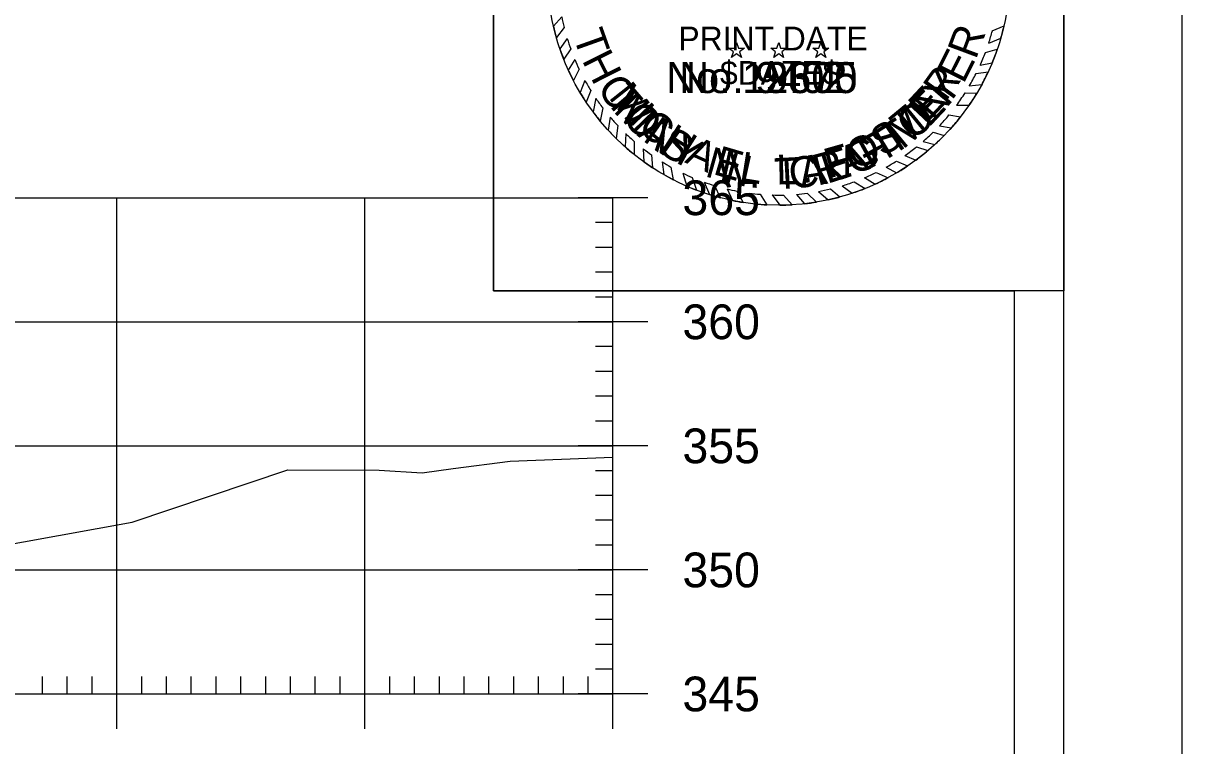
# Model space of a CAD drawing. Extents: x 1368910 to 1369601, y 380116 to 380950.
# Drawn here: x 1369553.81 to 1369600.52, y 380680.67 to 380709.8 of the extents above; entities that cross this region are included whole.
import ezdxf

# ---------------------------------------------------------------- set-up
doc = ezdxf.new("R2010")
doc.units = 0
for name, color, linetype in [('R_Axis', 7, 'Continuous'), ('R_Axis Annot', 7, 'Continuous'), ('R_Border', 7, 'Continuous'), ('R_Exist Surface', 7, 'Continuous'), ('R_Grid', 7, 'Continuous'), ('R_No Plot', 7, 'Continuous'), ('STAMP_PE_CRAFTON', 7, 'Continuous'), ('STAMP_PE_FOSTER', 7, 'Continuous'), ('STAMP_PE_SEAL-INFO', 7, 'Continuous'), ('STAMP_PE_TAEGTMEYER', 7, 'Continuous'), ('STAMP_PE_TXT', 7, 'Continuous'), ('STAMP_PRELIMINARY', 7, 'Continuous')]:
    doc.layers.add(name, color=color, linetype=linetype)

msp = doc.modelspace()

# ---------------------------------------------------------------- linework, layer by layer
at = {"layer": 'R_Axis'}
for p, q in [((1369578.99, 380702.759), (1369576.19, 380702.759)), ((1369577.59, 380682.759), (1369577.59, 380702.759)), ((1369577.59, 380701.759), (1369576.89, 380701.759)), ((1369577.59, 380700.759), (1369576.89, 380700.759)), ((1369577.59, 380699.759), (1369576.89, 380699.759)), ((1369577.59, 380698.759), (1369576.89, 380698.759)), ((1369578.99, 380697.759), (1369576.19, 380697.759)), ((1369577.59, 380696.759), (1369576.89, 380696.759)), ((1369577.59, 380695.759), (1369576.89, 380695.759)), ((1369577.59, 380694.759), (1369576.89, 380694.759)), ((1369577.59, 380693.759), (1369576.89, 380693.759)), ((1369578.99, 380692.759), (1369576.19, 380692.759)), ((1369577.59, 380691.759), (1369576.89, 380691.759)), ((1369577.59, 380690.759), (1369576.89, 380690.759)), ((1369577.59, 380689.759), (1369576.89, 380689.759)), ((1369577.59, 380688.759), (1369576.89, 380688.759)), ((1369578.99, 380687.759), (1369576.19, 380687.759)), ((1369577.59, 380686.759), (1369576.89, 380686.759)), ((1369577.59, 380685.759), (1369576.89, 380685.759)), ((1369577.59, 380684.759), (1369576.89, 380684.759)), ((1369557.59, 380681.359), (1369557.59, 380684.159)), ((1369567.59, 380681.359), (1369567.59, 380684.159)), ((1369577.59, 380681.359), (1369577.59, 380684.159)), ((1369577.59, 380683.759), (1369576.89, 380683.759)), ((1369554.59, 380682.759), (1369554.59, 380683.459)), ((1369555.59, 380682.759), (1369555.59, 380683.459)), ((1369556.59, 380682.759), (1369556.59, 380683.459)), ((1369558.59, 380682.759), (1369558.59, 380683.459)), ((1369559.59, 380682.759), (1369559.59, 380683.459)), ((1369560.59, 380682.759), (1369560.59, 380683.459)), ((1369561.59, 380682.759), (1369561.59, 380683.459)), ((1369562.59, 380682.759), (1369562.59, 380683.459)), ((1369563.59, 380682.759), (1369563.59, 380683.459)), ((1369564.59, 380682.759), (1369564.59, 380683.459)), ((1369565.59, 380682.759), (1369565.59, 380683.459)), ((1369566.59, 380682.759), (1369566.59, 380683.459)), ((1369568.59, 380682.759), (1369568.59, 380683.459)), ((1369569.59, 380682.759), (1369569.59, 380683.459)), ((1369570.59, 380682.759), (1369570.59, 380683.459)), ((1369571.59, 380682.759), (1369571.59, 380683.459)), ((1369572.59, 380682.759), (1369572.59, 380683.459)), ((1369573.59, 380682.759), (1369573.59, 380683.459)), ((1369574.59, 380682.759), (1369574.59, 380683.459)), ((1369575.59, 380682.759), (1369575.59, 380683.459)), ((1369576.59, 380682.759), (1369576.59, 380683.459)), ((1369297.59, 380682.759), (1369577.59, 380682.759)), ((1369578.99, 380682.759), (1369576.19, 380682.759))]:
    msp.add_line(p, q, dxfattribs=at)
at = {"layer": 'R_Border'}
msp.add_line((1369595.77, 380527.759), (1369595.77, 380733.219), dxfattribs=at)
at = {"layer": 'R_Exist Surface'}
msp.add_lwpolyline([(1369517.72, 380691.662), (1369530.654, 380692.291), (1369534.092, 380690.01), (1369537.049, 380687.943), (1369544.245, 380688.244), (1369546.58, 380688.221), (1369549.426, 380688.092), (1369558.204, 380689.69), (1369564.489, 380691.792), (1369568.163, 380691.776), (1369569.894, 380691.676), (1369571.144, 380691.841), (1369573.442, 380692.14), (1369577.59, 380692.301)], dxfattribs=at)
at = {"layer": 'R_Grid'}
for p, q in [((1369297.59, 380702.759), (1369577.59, 380702.759)), ((1369557.59, 380682.759), (1369557.59, 380702.759)), ((1369567.59, 380682.759), (1369567.59, 380702.759)), ((1369577.59, 380682.759), (1369577.59, 380702.759)), ((1369297.59, 380697.759), (1369577.59, 380697.759)), ((1369297.59, 380692.759), (1369577.59, 380692.759)), ((1369297.59, 380687.759), (1369577.59, 380687.759)), ((1369297.59, 380682.759), (1369577.59, 380682.759))]:
    msp.add_line(p, q, dxfattribs=at)
at = {"layer": 'R_No Plot'}
for points in [[(1369267.182, 380737.113), (1369600.522, 380737.113), (1369600.522, 380523.776), (1369267.182, 380523.776)], [(1369593.77, 380632.489), (1369281.59, 380632.489), (1369281.59, 380731.219), (1369531.13, 380731.219), (1369531.13, 380721.339), (1369548.67, 380721.339), (1369572.77, 380721.339), (1369572.77, 380699.006), (1369593.77, 380699.006)], [(1369281.59, 380731.219), (1369531.13, 380731.219), (1369531.13, 380721.339), (1369548.67, 380721.339), (1369572.77, 380721.339), (1369572.77, 380699.006), (1369593.77, 380699.006), (1369593.77, 380529.759), (1369281.59, 380529.759)], [(1369572.77, 380723.339), (1369595.77, 380723.339), (1369595.77, 380699.006), (1369572.77, 380699.006)]]:
    msp.add_lwpolyline(points, close=True, dxfattribs=at)
at = {"layer": 'STAMP_PE_SEAL-INFO'}
for p, q in [((1369575.527, 380710.046), (1369575.188, 380709.678)), ((1369575.621, 380709.627), (1369575.308, 380709.212)), ((1369592.883, 380709.488), (1369593.355, 380709.69)), ((1369575.744, 380709.18), (1369575.45, 380708.762)), ((1369592.736, 380708.994), (1369593.227, 380709.195)), ((1369575.885, 380708.757), (1369575.604, 380708.345)), ((1369592.602, 380708.614), (1369593.084, 380708.745)), ((1369576.052, 380708.331), (1369575.79, 380707.908)), ((1369576.223, 380707.947), (1369575.996, 380707.486)), ((1369592.227, 380707.763), (1369592.715, 380707.832)), ((1369592.388, 380708.1), (1369592.876, 380708.196)), ((1369576.458, 380707.489), (1369576.267, 380706.999)), ((1369591.954, 380707.265), (1369592.455, 380707.319)), ((1369576.694, 380707.085), (1369576.51, 380706.614)), ((1369591.783, 380706.984), (1369592.26, 380706.978)), ((1369576.896, 380706.773), (1369576.787, 380706.221)), ((1369577.177, 380706.383), (1369577.075, 380705.852)), ((1369591.443, 380706.49), (1369591.948, 380706.493)), ((1369577.481, 380706.005), (1369577.394, 380705.485)), ((1369591.135, 380706.096), (1369591.597, 380706.017)), ((1369577.784, 380705.668), (1369577.722, 380705.146)), ((1369590.752, 380705.663), (1369591.229, 380705.578)), ((1369578.106, 380705.343), (1369578.076, 380704.813)), ((1369578.45, 380705.03), (1369578.447, 380704.501)), ((1369590.091, 380705.031), (1369590.563, 380704.903)), ((1369590.497, 380705.404), (1369590.938, 380705.266)), ((1369578.81, 380704.735), (1369578.829, 380704.211)), ((1369579.149, 380704.486), (1369579.185, 380703.968)), ((1369589.821, 380704.807), (1369590.288, 380704.662)), ((1369579.576, 380704.204), (1369579.637, 380703.692)), ((1369589.016, 380704.236), (1369589.466, 380704.041)), ((1369589.36, 380704.464), (1369589.799, 380704.275)), ((1369579.926, 380703.998), (1369580.017, 380703.485)), ((1369580.407, 380703.748), (1369580.564, 380703.227)), ((1369580.78, 380703.58), (1369580.953, 380703.069)), ((1369587.735, 380703.569), (1369588.158, 380703.308)), ((1369588.194, 380703.778), (1369588.678, 380703.566)), ((1369588.602, 380703.991), (1369589.019, 380703.759)), ((1369581.272, 380703.387), (1369581.482, 380702.885)), ((1369581.682, 380703.252), (1369581.908, 380702.763)), ((1369582.19, 380703.114), (1369582.402, 380702.648)), ((1369586.363, 380703.117), (1369586.741, 380702.792)), ((1369586.823, 380703.241), (1369587.239, 380702.944)), ((1369587.315, 380703.404), (1369587.758, 380703.136)), ((1369582.587, 380703.028), (1369582.834, 380702.57)), ((1369583.088, 380702.947), (1369583.328, 380702.506)), ((1369583.524, 380702.899), (1369583.798, 380702.471)), ((1369584.009, 380702.872), (1369584.311, 380702.459)), ((1369584.469, 380702.87), (1369584.812, 380702.474)), ((1369584.987, 380702.897), (1369585.313, 380702.517)), ((1369585.425, 380702.943), (1369585.798, 380702.585)), ((1369585.871, 380703.013), (1369586.259, 380702.673))]:
    msp.add_line(p, q, dxfattribs=at)
for radius, start, end in [(9.323, 193.0369, 195.9973), (8.914, 191.2274, 193.9858), (9.323, 343.8925, 347.035), (8.914, 196.9675, 199.8353), (8.914, 341.777, 345.0925), (9.323, 198.8967, 201.6281), (9.323, 337.3837, 340.9933), (8.914, 202.7761, 205.4791), (8.914, 335.6038, 339.1858), (9.323, 204.5479, 207.4328), (8.914, 329.5549, 333.2076), (9.323, 331.4037, 334.9332), (8.914, 208.7883, 211.7934), (9.323, 210.8636, 213.6571), (8.914, 323.5851, 327.4407), (9.323, 325.4405, 328.9872), (8.914, 214.1838, 217.2747), (9.323, 216.6115, 219.491), (8.914, 220.3909, 223.3056), (8.914, 316.6531, 320.3711), (9.323, 318.2846, 321.8043), (9.323, 222.48, 225.3801), (8.914, 226.2494, 229.2407), (8.914, 310.7744, 314.3161), (9.323, 312.4518, 315.6633), (9.323, 228.3665, 231.348), (8.914, 232.229, 234.9336), (8.914, 304.823, 308.5143), (9.323, 306.3721, 310.208), (9.323, 234.295, 236.9452), (8.914, 238.2223, 240.8353), (8.914, 299.0768, 302.1724), (9.323, 300.621, 303.8703), (9.323, 240.1977, 242.8613), (8.914, 244.3204, 246.9486), (8.914, 292.8745, 296.1185), (9.323, 294.6481, 298.2166), (9.323, 246.576, 249.1558), (8.914, 250.3491, 253.1216), (8.914, 256.505, 259.1192), (8.914, 280.3459, 283.5814), (8.914, 286.6423, 289.9783), (9.323, 288.5709, 291.9733), (9.323, 252.5967, 255.3252), (9.323, 258.4433, 261.1398), (8.914, 262.3783, 265.2012), (8.914, 268.3215, 271.277), (8.914, 274.6157, 277.4486), (9.323, 282.3199, 285.3702), (9.323, 264.1978, 267.1009), (9.323, 270.2548, 273.3361), (9.323, 276.4239, 279.4357)]:
    msp.add_arc((1369584.27, 380711.781), radius, start, end, dxfattribs=at)
at = {"layer": 'STAMP_PE_TXT'}
for p, q in [((1369582.449, 380708.646), (1369582.251, 380708.79)), ((1369582.251, 380708.79), (1369582.496, 380708.79)), ((1369582.496, 380708.79), (1369582.572, 380709.023)), ((1369582.572, 380709.023), (1369582.648, 380708.79)), ((1369582.648, 380708.79), (1369582.893, 380708.79)), ((1369582.893, 380708.79), (1369582.695, 380708.646)), ((1369584.147, 380708.646), (1369583.949, 380708.79)), ((1369583.949, 380708.79), (1369584.194, 380708.79)), ((1369584.194, 380708.79), (1369584.27, 380709.023)), ((1369584.27, 380709.023), (1369584.346, 380708.79)), ((1369584.346, 380708.79), (1369584.591, 380708.79)), ((1369584.591, 380708.79), (1369584.393, 380708.646)), ((1369585.845, 380708.646), (1369585.647, 380708.79)), ((1369585.647, 380708.79), (1369585.892, 380708.79)), ((1369585.892, 380708.79), (1369585.968, 380709.023)), ((1369585.968, 380709.023), (1369586.044, 380708.79)), ((1369586.044, 380708.79), (1369586.289, 380708.79)), ((1369586.289, 380708.79), (1369586.091, 380708.646)), ((1369582.374, 380708.413), (1369582.449, 380708.646)), ((1369582.572, 380708.557), (1369582.374, 380708.413)), ((1369582.77, 380708.413), (1369582.572, 380708.557)), ((1369582.695, 380708.646), (1369582.77, 380708.413)), ((1369584.072, 380708.413), (1369584.147, 380708.646)), ((1369584.27, 380708.557), (1369584.072, 380708.413)), ((1369584.468, 380708.413), (1369584.27, 380708.557)), ((1369584.393, 380708.646), (1369584.468, 380708.413)), ((1369585.77, 380708.413), (1369585.845, 380708.646)), ((1369585.968, 380708.557), (1369585.77, 380708.413)), ((1369586.166, 380708.413), (1369585.968, 380708.557)), ((1369586.091, 380708.646), (1369586.166, 380708.413))]:
    msp.add_line(p, q, dxfattribs=at)
at = {"layer": 'STAMP_PRELIMINARY'}
msp.add_circle((1369584.27, 380711.781), 9.323, dxfattribs=at)

# ---------------------------------------------------------------- texts
at = {"layer": 'R_Axis Annot'}
for s, p in [('365', (1369580.39, 380702.059)), ('360', (1369580.39, 380697.059)), ('355', (1369580.39, 380692.059)), ('350', (1369580.39, 380687.059)), ('345', (1369580.39, 380682.059))]:
    msp.add_text(s, height=1.4, dxfattribs=at).set_placement(p)
at = {"layer": 'STAMP_PE_CRAFTON'}
msp.add_text('No. 12370', height=1.25, dxfattribs=at).set_placement((1369579.732, 380706.978))
for s, rotation, p in [('T', 310.7442, (1369577.236, 380706.679)), ('N', 49.2411, (1369590.552, 380705.803)), ('O', 317.6422, (1369577.903, 380705.868)), ('O', 41.8391, (1369589.705, 380705.022)), ('N', 324.4537, (1369578.749, 380705.083)), ('T', 34.1136, (1369588.847, 380704.42)), ('Y', 331.1686, (1369579.782, 380704.367)), ('F', 28.7821, (1369587.931, 380703.911)), ('N', 347.4752, (1369581.837, 380703.451)), ('R', 14.8189, (1369585.838, 380703.237)), ('A', 20.5125, (1369586.951, 380703.537)), ('C', 6.0117, (1369584.741, 380703.123)), ('.', 356.8926, (1369583.066, 380703.174))]:
    msp.add_text(s, height=1.25, rotation=rotation, dxfattribs=at).set_placement(p)
at = {"layer": 'STAMP_PE_FOSTER'}
msp.add_text('No. 9402', height=1.25, dxfattribs=at).set_placement((1369580.256, 380706.978))
for s, rotation, p in [('R', 54.5031, (1369590.994, 380706.592)), ('M', 308.339, (1369577.386, 380706.803)), ('E', 46.9613, (1369590.271, 380705.771)), ('I', 314.1842, (1369578.184, 380705.866)), ('T', 39.4194, (1369589.412, 380705.021)), ('C', 319.8733, (1369578.538, 380705.513)), ('H', 327.7235, (1369579.467, 380704.776)), ('S', 31.7234, (1369588.461, 380704.394)), ('A', 335.7276, (1369580.448, 380704.194)), ('O', 23.719, (1369587.349, 380703.864)), ('E', 343.5779, (1369581.585, 380703.724)), ('L', 350.8115, (1369582.644, 380703.447)), ('L', 1.2666, (1369584.183, 380703.29)), ('F', 15.8691, (1369586.305, 380703.536)), ('.', 6.8035, (1369585.23, 380703.348))]:
    msp.add_text(s, height=1.2, rotation=rotation, dxfattribs=at).set_placement(p)
at = {"layer": 'STAMP_PE_TAEGTMEYER'}
for s, rotation, p in [('T', 289.646, (1369575.964, 380709.292)), ('R', 69.57, (1369592.215, 380708.296)), ('H', 296.7339, (1369576.324, 380708.307)), ('E', 63.0984, (1369591.716, 380707.314)), ('Y', 53.9986, (1369591.047, 380706.374)), ('O', 303.7708, (1369576.917, 380707.199)), ('M', 314.2033, (1369577.572, 380706.248)), ('E', 46.8094, (1369590.308, 380705.559)), ('M', 39.3, (1369589.268, 380704.68)), ('A', 321.0594, (1369578.534, 380705.283)), ('S', 327.8239, (1369579.36, 380704.639)), ('T', 31.466, (1369588.37, 380704.136)), ('G', 23.3052, (1369587.27, 380703.643)), ('N', 344.2727, (1369581.257, 380703.633)), ('A', 8.9826, (1369585.181, 380703.157)), ('E', 17.6836, (1369586.22, 380703.313)), ('T', 3.0061, (1369584.134, 380703.102)), ('.', 350.6464, (1369582.469, 380703.301))]:
    msp.add_text(s, height=1.25, rotation=rotation, dxfattribs=at).set_placement(p)
msp.add_text('No. 19605', height=1.25, dxfattribs=at).set_placement((1369579.732, 380706.978))
at = {"layer": 'STAMP_PRELIMINARY'}
for s, p in [('PRINT DATE', (1369580.227, 380708.697)), ('$DATE$', (1369581.904, 380707.312))]:
    msp.add_text(s, height=0.96, dxfattribs=at).set_placement(p)

doc.saveas('drawing.dxf')
